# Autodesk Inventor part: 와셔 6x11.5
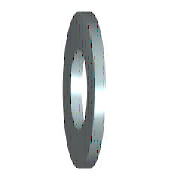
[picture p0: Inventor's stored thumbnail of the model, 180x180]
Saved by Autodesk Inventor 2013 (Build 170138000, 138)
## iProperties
IsCustomPart: 1
Created: 2012-02
Part Number: 와셔 6x11.5
Material: 강철, 연강
Description: 평면 와셔
Document SubType Name: Modeling
Standard: KS B 1326
Designer: mduedu
Standards Organization: KS
Language: ko-KR
Size Designation: 6x11.5
Categories: <MemberInstance><Categories><Category DisplayName="조임쇠" InternalName="e4da775c-781d-43d5-af7c-5136215cf5a6" Mnemonic="FSTN"><Category DisplayName="와셔" InternalN
Density: 1 g/cm^3
Author: mduedu
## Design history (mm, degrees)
sketch "스케치"
  geometry: C1 r 5.75 at (0, 0); C2 r 3.2 at (0, 0); 1 further point
  constraints: 2 centre point, 2 coincident
  dimensions: "d0" = 6.4 diameter of C2 (= SD1); "d1" = 11.5 diameter of C1 (= SD2)
extrude "본체" new body sketch "스케치" distance "d2" = 1.6 (= SD); taper "d3" = 0 deg
workaxis "Work Axis1"
workplane "Work Plane1"
body "Solid1"
other parameters: "SD1" = 6.4 [user parameter; used in 1 equation term], "SD2" = 11.5 [user parameter; used in 1 equation term], "SD" = 1.6 [user parameter; used in 1 equation term], "d4" = 0, "d5" = 0, "d6" = 0, "d7" = 0, "NND" = 6 [user parameter]
